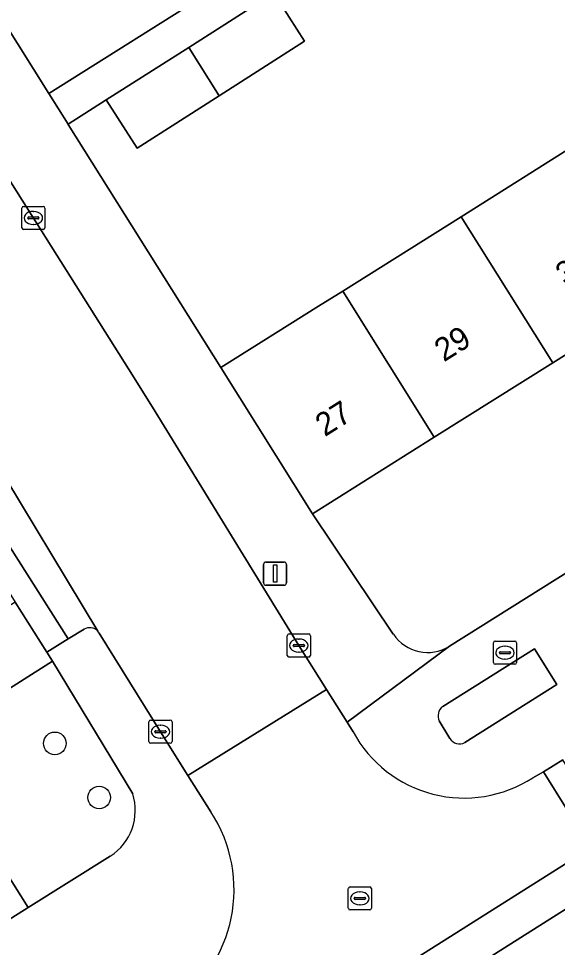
# Model space of a CAD drawing. Extents: x 160077 to 160948, y 386481 to 387498.
# Drawn here: x 160388.91 to 160412.23, y 387188.2 to 387228.36 of the extents above; entities that cross this region are included whole.
import ezdxf

# ---------------------------------------------------------------- set-up
doc = ezdxf.new("R2010")
doc.units = 0
for name, color, linetype in [('IMGEO_Boom', 7, 'Continuous'), ('IMGEO_Brandkraan', 7, 'Continuous'), ('IMGEO_Erf', 7, 'Continuous'), ('IMGEO_Groenvoorziening', 7, 'Continuous'), ('IMGEO_Kolk', 7, 'Continuous'), ('IMGEO_Lichtmast', 7, 'Continuous'), ('IMGEO_Muur', 7, 'Continuous'), ('IMGEO_Pand', 7, 'Continuous'), ('IMGEO_Pand_nummerreeks', 7, 'Continuous'), ('IMGEO_Rijbaan_lokaal_gesloten', 7, 'Continuous'), ('IMGEO_Rijbaan_lokaal_open', 7, 'Continuous'), ('IMGEO_Rioolput', 7, 'Continuous'), ('IMGEO_Voetpad_open', 7, 'Continuous')]:
    doc.layers.add(name, color=color, linetype=linetype)

msp = doc.modelspace()

# ---------------------------------------------------------------- linework, layer by layer
at = {"layer": 'IMGEO_Boom'}
for centre in [(160390.483, 387197.026), (160392.401, 387194.689)]:
    msp.add_circle(centre, 0.489, dxfattribs=at)
at = {"layer": 'IMGEO_Brandkraan'}
for p, q in [((160409.457, 387200.52), (160409.457, 387201.372)), ((160409.532, 387201.446), (160410.384, 387201.446)), ((160410.458, 387201.372), (160410.458, 387200.52)), ((160409.716, 387200.94), (160409.716, 387200.952)), ((160410.154, 387200.903), (160409.756, 387200.903)), ((160409.759, 387200.989), (160410.157, 387200.989)), ((160409.945, 387201.226), (160409.97, 387201.226)), ((160410.2, 387200.952), (160410.2, 387200.94)), ((160409.968, 387200.666), (160409.943, 387200.666)), ((160410.384, 387200.446), (160409.532, 387200.446))]:
    msp.add_line(p, q, dxfattribs=at)
for points in [[(160409.457, 387200.52), (160409.457, 387201.372)], [(160409.532, 387201.446), (160410.384, 387201.446)], [(160410.458, 387201.372), (160410.458, 387200.52)], [(160410.384, 387200.446), (160409.532, 387200.446)]]:
    msp.add_lwpolyline(points, dxfattribs=at)
for centre, radius, start, end in [((160409.534, 387201.37), 0.0765, 91.552, 178.448), ((160409.534, 387201.37), 0.0765, 91.552, 178.448), ((160410.382, 387201.37), 0.0765, 1.552, 88.448), ((160410.382, 387201.37), 0.0765, 1.552, 88.448), ((160409.756, 387200.949), 0.0403, 85.8775, 175.7526), ((160409.753, 387200.939), 0.0366, 178.938, 274.7102), ((160410.157, 387200.946), 0.043, 264.8664, 352.4533), ((160410.161, 387200.951), 0.0386, 1.7309, 96.639), ((160409.534, 387200.522), 0.0765, 181.552, 268.448), ((160409.534, 387200.522), 0.0765, 181.552, 268.448), ((160410.382, 387200.522), 0.0765, 271.552, 358.448), ((160410.382, 387200.522), 0.0765, 271.552, 358.448)]:
    msp.add_arc(centre, radius, start, end, dxfattribs=at)
for centre, major_axis, ratio, start_param, end_param in [((160409.944, 387200.946), (-0.387, 0.002), 0.722429, 4.712389, 7.853982), ((160409.969, 387200.946), (-0.39, 0.002), 0.717154, 1.570796, 4.712389)]:
    msp.add_ellipse(centre, major_axis=major_axis, ratio=ratio, start_param=start_param, end_param=end_param, dxfattribs=at)
at = {"layer": 'IMGEO_Erf'}
for points in [[(160386.208, 387231.51), (160390.216, 387225.126), (160397.563, 387229.739), (160405.257, 387234.57), (160405.257, 387235.583), (160404.582, 387239.961), (160403.966, 387243.954), (160406.177, 387244.295), (160405.626, 387247.865), (160403.341, 387247.513), (160402.666, 387251.891)], [(160467.691, 387238.95), (160463.439, 387245.729), (160458.165, 387242.42), (160453.038, 387239.204), (160447.912, 387235.987), (160442.785, 387232.771), (160437.658, 387229.555), (160432.533, 387226.339), (160427.406, 387223.123), (160422.279, 387219.906), (160417.152, 387216.69), (160412.026, 387213.474), (160406.899, 387210.257), (160401.625, 387206.948), (160405.127, 387201.741)], [(160407.555, 387201.225), (160467.691, 387238.95)], [(160413.215, 387237.704), (160410.206, 387235.897), (160411.535, 387233.814), (160407.877, 387231.478), (160404.291, 387229.188), (160402.961, 387231.271), (160399.953, 387229.465), (160401.282, 387227.382), (160397.585, 387225.021), (160394.038, 387222.756), (160392.708, 387224.839), (160391.05, 387223.798), (160391.058, 387223.785), (160397.66, 387213.268), (160401.896, 387215.926), (160402.935, 387216.578), (160408.062, 387219.794), (160413.188, 387223.01)]]:
    msp.add_lwpolyline(points, dxfattribs=at)
msp.add_arc((160406.608, 387202.739), 1.785, 213.9661, 302.0378, dxfattribs=at)
at = {"layer": 'IMGEO_Groenvoorziening'}
for points in [[(160412.198, 387199.569), (160411.238, 387201.111), (160407.263, 387198.622)], [(160390.386, 387200.575), (160384.822, 387197.06), (160389.327, 387189.925), (160392.881, 387192.147)], [(160393.851, 387194.847), (160390.386, 387200.575)], [(160408.228, 387197.057), (160412.198, 387199.569)], [(160407.115, 387197.993), (160407.574, 387197.243)]]:
    msp.add_lwpolyline(points, dxfattribs=at)
for centre, radius, start, end in [((160407.575, 387198.217), 0.512, 127.6222, 205.8967), ((160407.999, 387197.493), 0.493, 210.5226, 297.7255), ((160391.594, 387194.134), 2.367, 302.934, 17.5434)]:
    msp.add_arc(centre, radius, start, end, dxfattribs=at)
at = {"layer": 'IMGEO_Kolk'}
for p, q in [((160389.051, 387219.315), (160389.051, 387220.167)), ((160389.126, 387220.241), (160389.978, 387220.241)), ((160390.052, 387220.167), (160390.052, 387219.315)), ((160389.31, 387219.735), (160389.31, 387219.747)), ((160389.353, 387219.784), (160389.751, 387219.784)), ((160389.539, 387220.021), (160389.564, 387220.021)), ((160389.794, 387219.747), (160389.794, 387219.735)), ((160389.748, 387219.698), (160389.35, 387219.698)), ((160389.562, 387219.461), (160389.537, 387219.461)), ((160389.978, 387219.241), (160389.126, 387219.241)), ((160400.539, 387200.828), (160400.539, 387201.68)), ((160400.614, 387201.754), (160401.466, 387201.754)), ((160401.54, 387201.68), (160401.54, 387200.828)), ((160400.841, 387201.297), (160401.239, 387201.297)), ((160401.027, 387201.534), (160401.052, 387201.534)), ((160400.798, 387201.248), (160400.798, 387201.26)), ((160401.236, 387201.211), (160400.838, 387201.211)), ((160401.05, 387200.974), (160401.025, 387200.974)), ((160401.282, 387201.26), (160401.282, 387201.248)), ((160401.466, 387200.754), (160400.614, 387200.754)), ((160394.549, 387197.104), (160394.549, 387197.956)), ((160394.624, 387198.03), (160395.476, 387198.03)), ((160395.037, 387197.81), (160395.062, 387197.81)), ((160395.55, 387197.956), (160395.55, 387197.104)), ((160394.808, 387197.524), (160394.808, 387197.536)), ((160395.246, 387197.487), (160394.848, 387197.487)), ((160394.851, 387197.573), (160395.249, 387197.573)), ((160395.06, 387197.25), (160395.035, 387197.25)), ((160395.292, 387197.536), (160395.292, 387197.524)), ((160395.476, 387197.03), (160394.624, 387197.03))]:
    msp.add_line(p, q, dxfattribs=at)
for points in [[(160389.051, 387219.315), (160389.051, 387220.167)], [(160389.126, 387220.241), (160389.978, 387220.241)], [(160390.052, 387220.167), (160390.052, 387219.315)], [(160389.978, 387219.241), (160389.126, 387219.241)], [(160400.539, 387200.828), (160400.539, 387201.68)], [(160400.614, 387201.754), (160401.466, 387201.754)], [(160401.54, 387201.68), (160401.54, 387200.828)], [(160401.466, 387200.754), (160400.614, 387200.754)], [(160394.549, 387197.104), (160394.549, 387197.956)], [(160394.624, 387198.03), (160395.476, 387198.03)], [(160395.55, 387197.956), (160395.55, 387197.104)], [(160395.476, 387197.03), (160394.624, 387197.03)]]:
    msp.add_lwpolyline(points, dxfattribs=at)
for centre, radius, start, end in [((160389.128, 387220.165), 0.0765, 91.552, 178.448), ((160389.128, 387220.165), 0.0765, 91.552, 178.448), ((160389.976, 387220.165), 0.0765, 1.552, 88.448), ((160389.976, 387220.165), 0.0765, 1.552, 88.448), ((160389.35, 387219.744), 0.0403, 85.8775, 175.7526), ((160389.755, 387219.746), 0.0386, 1.7309, 96.639), ((160389.347, 387219.734), 0.0366, 178.938, 274.7102), ((160389.751, 387219.741), 0.043, 264.8664, 352.4533), ((160389.128, 387219.317), 0.0765, 181.552, 268.448), ((160389.128, 387219.317), 0.0765, 181.552, 268.448), ((160389.976, 387219.317), 0.0765, 271.552, 358.448), ((160389.976, 387219.317), 0.0765, 271.552, 358.448), ((160400.616, 387201.678), 0.0765, 91.552, 178.448), ((160400.616, 387201.678), 0.0765, 91.552, 178.448), ((160401.464, 387201.678), 0.0765, 1.552, 88.448), ((160401.464, 387201.678), 0.0765, 1.552, 88.448), ((160400.838, 387201.257), 0.0403, 85.8775, 175.7526), ((160401.243, 387201.259), 0.0386, 1.7309, 96.639), ((160400.835, 387201.247), 0.0366, 178.938, 274.7102), ((160401.239, 387201.254), 0.043, 264.8664, 352.4533), ((160400.616, 387200.83), 0.0765, 181.552, 268.448), ((160400.616, 387200.83), 0.0765, 181.552, 268.448), ((160401.464, 387200.83), 0.0765, 271.552, 358.448), ((160401.464, 387200.83), 0.0765, 271.552, 358.448), ((160394.626, 387197.954), 0.0765, 91.552, 178.448), ((160394.626, 387197.954), 0.0765, 91.552, 178.448), ((160395.474, 387197.954), 0.0765, 1.552, 88.448), ((160395.474, 387197.954), 0.0765, 1.552, 88.448), ((160394.848, 387197.533), 0.0403, 85.8775, 175.7526), ((160394.845, 387197.523), 0.0366, 178.938, 274.7102), ((160395.249, 387197.53), 0.043, 264.8664, 352.4533), ((160395.253, 387197.535), 0.0386, 1.7309, 96.639), ((160394.626, 387197.106), 0.0765, 181.552, 268.448), ((160394.626, 387197.106), 0.0765, 181.552, 268.448), ((160395.474, 387197.106), 0.0765, 271.552, 358.448), ((160395.474, 387197.106), 0.0765, 271.552, 358.448)]:
    msp.add_arc(centre, radius, start, end, dxfattribs=at)
for centre, major_axis, ratio, start_param, end_param in [((160389.538, 387219.741), (-0.387, 0.002), 0.722429, 4.712389, 7.853982), ((160389.563, 387219.741), (-0.39, 0.002), 0.717154, 1.570796, 4.712389), ((160401.026, 387201.254), (-0.387, 0.002), 0.722429, 4.712389, 7.853982), ((160401.051, 387201.254), (-0.39, 0.002), 0.717154, 1.570796, 4.712389), ((160395.036, 387197.53), (-0.387, 0.002), 0.722429, 4.712389, 7.853982), ((160395.061, 387197.53), (-0.39, 0.002), 0.717154, 1.570796, 4.712389)]:
    msp.add_ellipse(centre, major_axis=major_axis, ratio=ratio, start_param=start_param, end_param=end_param, dxfattribs=at)
at = {"layer": 'IMGEO_Lichtmast'}
for p, q in [((160399.515, 387203.964), (160399.515, 387204.764)), ((160399.515, 387204.764), (160399.515, 387203.964)), ((160399.615, 387204.864), (160400.405, 387204.864)), ((160400.405, 387204.864), (160399.615, 387204.864)), ((160400.505, 387204.764), (160400.505, 387203.964)), ((160400.505, 387203.964), (160400.505, 387204.764)), ((160400.405, 387203.864), (160399.615, 387203.864)), ((160399.615, 387203.864), (160400.405, 387203.864))]:
    msp.add_line(p, q, dxfattribs=at)
msp.add_lwpolyline([(160399.935, 387204.739), (160400.085, 387204.739), (160400.085, 387203.989), (160399.935, 387203.989), (160399.935, 387204.739)], dxfattribs=at)
for centre, start, end in [((160399.615, 387204.764), 90, 180), ((160399.615, 387204.764), 90, 180), ((160400.405, 387204.764), 0, 90), ((160400.405, 387204.764), 360, 90), ((160399.615, 387203.964), 180, 270), ((160399.615, 387203.964), 180, 270), ((160400.405, 387203.964), 270, 0), ((160400.405, 387203.964), 270, 0)]:
    msp.add_arc(centre, 0.1, start, end, dxfattribs=at)
at = {"layer": 'IMGEO_Muur'}
msp.add_lwpolyline([(160397.66, 387213.268), (160391.058, 387223.785)], dxfattribs=at)
at = {"layer": 'IMGEO_Pand'}
for points in [[(160397.585, 387225.021), (160401.282, 387227.382), (160399.953, 387229.465), (160396.272, 387227.115)], [(160397.585, 387225.021), (160396.272, 387227.115), (160392.708, 387224.839), (160394.038, 387222.756)], [(160412.026, 387213.474), (160417.152, 387216.69), (160413.188, 387223.01), (160408.062, 387219.794)], [(160406.899, 387210.257), (160412.026, 387213.474), (160408.062, 387219.794), (160402.935, 387216.578)], [(160401.625, 387206.948), (160406.899, 387210.257), (160402.935, 387216.578), (160401.896, 387215.926), (160397.66, 387213.268)], [(160390.386, 387200.575), (160390.137, 387200.969), (160388.769, 387203.134), (160383.205, 387199.619), (160384.822, 387197.06)]]:
    msp.add_lwpolyline(points, close=True, dxfattribs=at)
at = {"layer": 'IMGEO_Rijbaan_lokaal_gesloten'}
msp.add_lwpolyline([(160414.567, 387191.111), (160413.673, 387192.507), (160397.575, 387182.352), (160398.439, 387180.919)], close=True, dxfattribs=at)
at = {"layer": 'IMGEO_Rijbaan_lokaal_open'}
for points in [[(160363.189, 387278.751), (160367.156, 387253.21), (160367.704, 387249.631), (160367.846, 387248.68), (160369.755, 387240.738), (160373.09, 387232.545), (160375.851, 387228.204), (160387.661, 387209.599), (160392.339, 387201.873)], [(160392.405, 387201.787), (160395.05, 387197.53), (160396.242, 387195.64), (160402.235, 387199.358), (160401.04, 387201.254), (160394.82, 387211.374), (160393.915, 387212.833), (160383.125, 387229.912)], [(160403.384, 387197.523), (160403.123, 387197.94), (160402.235, 387199.358), (160396.242, 387195.64), (160397.229, 387194.072)], [(160395.505, 387185.588), (160397.575, 387182.352), (160413.673, 387192.507), (160411.623, 387195.791)], [(160411.623, 387195.791), (160411.166, 387195.541)]]:
    msp.add_lwpolyline(points, dxfattribs=at)
msp.add_lwpolyline([(160413.35, 387194.87), (160412.46, 387196.315), (160411.623, 387195.791), (160413.673, 387192.507), (160414.567, 387191.111), (160415.41, 387191.638), (160414.527, 387193.04)], close=True, dxfattribs=at)
for centre, radius, start, end in [((160391.958, 387201.512), 0.525, 31.5807, 43.4276), ((160408.194, 387200.139), 5.475, 208.5451, 302.8771), ((160392.083, 387190.701), 6.152, 303.7957, 33.2314)]:
    msp.add_arc(centre, radius, start, end, dxfattribs=at)
at = {"layer": 'IMGEO_Rioolput'}
for p, q in [((160403.18, 387189.898), (160403.18, 387190.75)), ((160403.255, 387190.824), (160404.107, 387190.824)), ((160403.668, 387190.604), (160403.693, 387190.604)), ((160404.181, 387190.75), (160404.181, 387189.898)), ((160403.439, 387190.318), (160403.439, 387190.33)), ((160403.877, 387190.281), (160403.479, 387190.281)), ((160403.482, 387190.367), (160403.88, 387190.367)), ((160403.691, 387190.044), (160403.666, 387190.044)), ((160403.923, 387190.33), (160403.923, 387190.318)), ((160404.107, 387189.824), (160403.255, 387189.824))]:
    msp.add_line(p, q, dxfattribs=at)
for points in [[(160403.18, 387189.898), (160403.18, 387190.75)], [(160403.255, 387190.824), (160404.107, 387190.824)], [(160404.181, 387190.75), (160404.181, 387189.898)], [(160404.107, 387189.824), (160403.255, 387189.824)]]:
    msp.add_lwpolyline(points, dxfattribs=at)
for centre, radius, start, end in [((160403.257, 387190.748), 0.0765, 91.552, 178.448), ((160403.257, 387190.748), 0.0765, 91.552, 178.448), ((160404.105, 387190.748), 0.0765, 1.552, 88.448), ((160404.105, 387190.748), 0.0765, 1.552, 88.448), ((160403.479, 387190.327), 0.0403, 85.8775, 175.7526), ((160403.476, 387190.317), 0.0366, 178.938, 274.7102), ((160403.88, 387190.324), 0.043, 264.8664, 352.4533), ((160403.884, 387190.329), 0.0386, 1.7309, 96.639), ((160403.257, 387189.9), 0.0765, 181.552, 268.448), ((160403.257, 387189.9), 0.0765, 181.552, 268.448), ((160404.105, 387189.9), 0.0765, 271.552, 358.448), ((160404.105, 387189.9), 0.0765, 271.552, 358.448)]:
    msp.add_arc(centre, radius, start, end, dxfattribs=at)
for centre, major_axis, ratio, start_param, end_param in [((160403.667, 387190.324), (-0.387, 0.002), 0.722429, 4.712389, 7.853982), ((160403.692, 387190.324), (-0.39, 0.002), 0.717154, 1.570796, 4.712389)]:
    msp.add_ellipse(centre, major_axis=major_axis, ratio=ratio, start_param=start_param, end_param=end_param, dxfattribs=at)
at = {"layer": 'IMGEO_Voetpad_open'}
for points in [[(160472.236, 387241.799), (160468.731, 387239.603), (160467.691, 387238.95), (160407.555, 387201.225), (160403.123, 387197.94), (160403.384, 387197.523)], [(160401.625, 387206.948), (160397.66, 387213.268), (160391.058, 387223.785), (160391.05, 387223.798), (160390.216, 387225.126), (160386.208, 387231.51)], [(160383.125, 387229.912), (160393.915, 387212.833), (160394.82, 387211.374), (160401.04, 387201.254), (160402.235, 387199.358), (160403.123, 387197.94), (160407.555, 387201.225)], [(160397.563, 387229.739), (160390.216, 387225.126), (160391.05, 387223.798), (160392.708, 387224.839), (160396.272, 387227.115), (160399.953, 387229.465)], [(160392.339, 387201.873), (160387.661, 387209.599), (160375.851, 387228.204)], [(160375.588, 387227.029), (160375.079, 387226.707), (160391.058, 387201.539), (160391.743, 387201.964)], [(160405.127, 387201.741), (160401.625, 387206.948)], [(160433.068, 387202.801), (160432.227, 387202.261), (160416.442, 387192.287), (160415.41, 387191.638), (160414.567, 387191.111), (160398.439, 387180.919), (160397.605, 387180.392), (160394.667, 387178.521), (160392.212, 387176.868)], [(160391.743, 387201.964), (160391.058, 387201.539), (160390.137, 387200.969), (160390.386, 387200.575), (160393.851, 387194.847)], [(160397.229, 387194.072), (160396.242, 387195.64), (160395.05, 387197.53), (160392.405, 387201.787)], [(160407.263, 387198.622), (160411.238, 387201.111), (160412.198, 387199.569)], [(160412.198, 387199.569), (160408.228, 387197.057)], [(160407.574, 387197.243), (160407.115, 387197.993)], [(160388.058, 387189.131), (160389.327, 387189.925), (160384.822, 387197.06)], [(160411.166, 387195.541), (160411.623, 387195.791), (160412.46, 387196.315)], [(160392.881, 387192.147), (160389.327, 387189.925), (160388.058, 387189.131), (160351.677, 387166.384), (160365.51, 387144.26), (160365.513, 387144.26), (160368.801, 387139.312), (160372.272, 387141.483)]]:
    msp.add_lwpolyline(points, dxfattribs=at)
msp.add_lwpolyline([(160375.079, 387226.707), (160374.219, 387226.164), (160375.836, 387223.605), (160377.452, 387221.046), (160379.069, 387218.487), (160380.686, 387215.928), (160382.302, 387213.37), (160383.919, 387210.811), (160385.536, 387208.252), (160387.153, 387205.693), (160388.769, 387203.134), (160390.137, 387200.969), (160391.058, 387201.539)], close=True, dxfattribs=at)
for centre, radius, start, end in [((160391.982, 387201.53), 0.495, 43.795, 118.8427), ((160391.982, 387201.53), 0.495, 43.795, 118.8427), ((160391.958, 387201.512), 0.525, 31.5807, 43.4276), ((160406.608, 387202.739), 1.785, 213.9661, 302.0378), ((160407.575, 387198.217), 0.512, 127.6222, 205.8967), ((160408.194, 387200.139), 5.475, 208.5451, 302.8771), ((160407.999, 387197.493), 0.493, 210.5226, 297.7255), ((160391.594, 387194.134), 2.367, 302.934, 17.5434), ((160392.083, 387190.701), 6.152, 303.7957, 33.2314)]:
    msp.add_arc(centre, radius, start, end, dxfattribs=at)

# ---------------------------------------------------------------- texts
at = {"layer": 'IMGEO_Pand_nummerreeks'}
for s, p in [('31', (160412.56, 387216.783)), ('29', (160407.313, 387213.491)), ('27', (160402.161, 387210.259))]:
    msp.add_text(s, height=1, rotation=32.1034, dxfattribs=at).set_placement(p)

doc.saveas('drawing.dxf')
